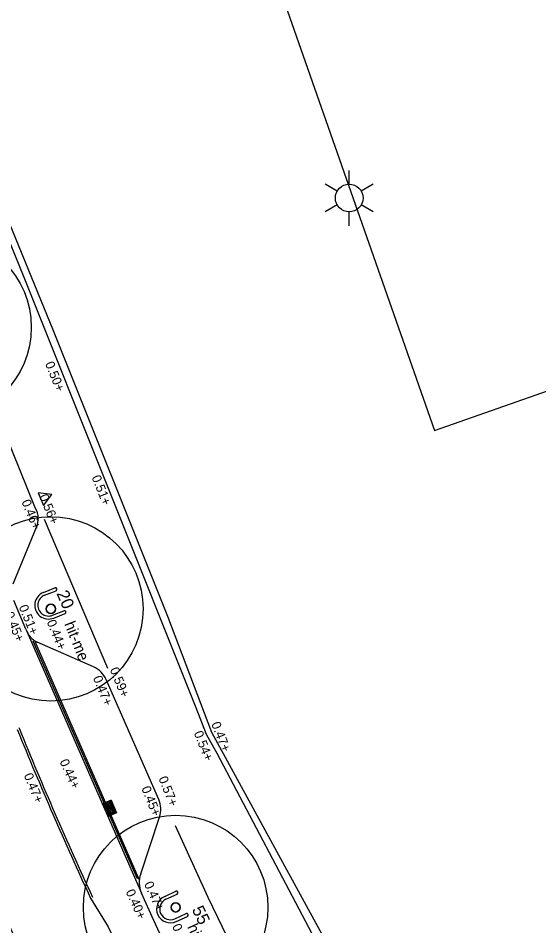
# Model space of a CAD drawing. Extents: x 122462 to 123306, y 485548 to 486417.
# Drawn here: x 122922.68 to 122939.61, y 485863.95 to 485893.49 of the extents above; entities that cross this region are included whole.
import ezdxf

# ---------------------------------------------------------------- set-up
doc = ezdxf.new("R2010")
doc.units = 0
for name, color, linetype in [('B-WE-GR-BOOM_BOOMDIAMETER', 7, 'Continuous'), ('B-WE-IE-TERREINAFSCHEIDING_KUNSTMATIG_HEKWERK-G', 7, 'Continuous'), ('B-WE-OG-HOOGTEPUNT-S', 7, 'Continuous'), ('B-WE-RI-HWA_KOLK-S', 7, 'Continuous'), ('B-WE-VH-KANTOPSLUITING_OPSLUITBAND_100X200-G', 7, 'Continuous'), ('B-WE-VH-KANTOPSLUITING_TROTTOIRBAND_130 150-G', 7, 'Continuous'), ('B-WE-VH-MATERIAALGRENS-G', 7, 'Continuous'), ('B-WE-VH-MATERIAALGRENS_ASFALT-G', 7, 'Continuous'), ('B-WE-VW-MARKERING_LANGS_STREEP_11_010-G', 7, 'Continuous'), ('iba7-verkeersbord rood', 7, 'Continuous'), ('Level 19', 7, 'Continuous'), ('Level 50', 7, 'Continuous'), ('N-WE-GR-BOOM-S', 7, 'Continuous'), ('V markering 1-1 10 cm', 7, 'Continuous'), ('V markering ononderbroken streep 10 cm', 7, 'Continuous'), ('V materiaalscheiding algemeen', 7, 'Continuous'), ('V meubilair trammast', 7, 'Continuous'), ('V Rails', 7, 'Continuous'), ('V RWS-band 115-225x250 mm specie', 7, 'Continuous')]:
    doc.layers.add(name, color=color, linetype=linetype)

msp = doc.modelspace()

# ---------------------------------------------------------------- linework, layer by layer
at = {"layer": 'B-WE-IE-TERREINAFSCHEIDING_KUNSTMATIG_HEKWERK-G'}
msp.add_lwpolyline([(122949.934, 485831.427), (122948.27, 485830.745), (122945.476, 485837.577), (122942.349, 485845.026), (122939.555, 485850.28), (122935.876, 485857.417), (122934.038, 485860.97), (122928.985, 485870.238), (122927.546, 485874.018), (122923.83, 485883.309), (122922.297, 485887.055), (122920.807, 485890.782), (122917.748, 485898.208), (122914.1, 485907.546), (122912.833, 485911.363), (122910.564, 485917.746), (122912.713, 485918.514)], dxfattribs=at)
at = {"layer": 'B-WE-RI-HWA_KOLK-S'}
for p, q in [((122925.702, 485868.036), (122925.427, 485867.917)), ((122925.605, 485867.504), (122925.427, 485867.917)), ((122925.694, 485868.016), (122925.446, 485867.909)), ((122925.694, 485868.016), (122925.861, 485867.631)), ((122925.702, 485868.036), (122925.881, 485867.623)), ((122925.613, 485867.524), (122925.446, 485867.909)), ((122925.881, 485867.623), (122925.605, 485867.504)), ((122925.861, 485867.631), (122925.613, 485867.524))]:
    msp.add_line(p, q, dxfattribs=at)
for points in [[(122925.662, 485867.982), (122925.493, 485867.909)], [(122925.506, 485867.879), (122925.675, 485867.953)], [(122925.682, 485867.936), (122925.513, 485867.863)], [(122925.68, 485867.966), (122925.675, 485867.977)], [(122925.7, 485867.92), (122925.695, 485867.931)], [(122925.488, 485867.896), (122925.493, 485867.885)], [(122925.508, 485867.85), (122925.513, 485867.839)], [(122925.526, 485867.833), (122925.695, 485867.907)], [(122925.528, 485867.804), (122925.532, 485867.793)], [(122925.702, 485867.89), (122925.533, 485867.817)], [(122925.546, 485867.788), (122925.715, 485867.861)], [(122925.548, 485867.758), (122925.552, 485867.747)], [(122925.722, 485867.844), (122925.553, 485867.771)], [(122925.565, 485867.742), (122925.735, 485867.815)], [(122925.567, 485867.712), (122925.572, 485867.701)], [(122925.742, 485867.798), (122925.573, 485867.725)], [(122925.585, 485867.696), (122925.754, 485867.769)], [(122925.587, 485867.666), (122925.592, 485867.655)], [(122925.762, 485867.752), (122925.592, 485867.679)], [(122925.605, 485867.65), (122925.774, 485867.723)], [(122925.607, 485867.62), (122925.612, 485867.609)], [(122925.781, 485867.707), (122925.612, 485867.633)], [(122925.625, 485867.604), (122925.794, 485867.677)], [(122925.801, 485867.661), (122925.632, 485867.588)], [(122925.645, 485867.558), (122925.814, 485867.631)], [(122925.72, 485867.874), (122925.715, 485867.885)], [(122925.74, 485867.828), (122925.735, 485867.839)], [(122925.76, 485867.782), (122925.755, 485867.793)], [(122925.779, 485867.736), (122925.775, 485867.747)], [(122925.799, 485867.69), (122925.795, 485867.701)], [(122925.819, 485867.644), (122925.814, 485867.655)], [(122925.627, 485867.574), (122925.632, 485867.563)]]:
    msp.add_lwpolyline(points, dxfattribs=at)
for centre, start, end in [((122925.666, 485867.973), 23.4005, 113.4005), ((122925.671, 485867.962), 293.4005, 23.4005), ((122925.686, 485867.927), 23.4005, 113.4005), ((122925.691, 485867.916), 293.4005, 23.4005), ((122925.497, 485867.9), 113.4005, 203.4005), ((122925.502, 485867.889), 203.4005, 293.4005), ((122925.517, 485867.854), 113.4005, 203.4005), ((122925.522, 485867.843), 203.4005, 293.4005), ((122925.537, 485867.808), 113.4005, 203.4005), ((122925.542, 485867.797), 203.4005, 293.4005), ((122925.557, 485867.762), 113.4005, 203.4005), ((122925.561, 485867.751), 203.4005, 293.4005), ((122925.577, 485867.716), 113.4005, 203.4005), ((122925.581, 485867.705), 203.4005, 293.4005), ((122925.596, 485867.67), 113.4005, 203.4005), ((122925.601, 485867.659), 203.4005, 293.4005), ((122925.616, 485867.624), 113.4005, 203.4005), ((122925.706, 485867.881), 23.4005, 113.4005), ((122925.711, 485867.87), 293.4005, 23.4005), ((122925.726, 485867.835), 23.4005, 113.4005), ((122925.731, 485867.824), 293.4005, 23.4005), ((122925.746, 485867.789), 23.4005, 113.4005), ((122925.75, 485867.778), 293.4005, 23.4005), ((122925.766, 485867.743), 23.4005, 113.4005), ((122925.77, 485867.732), 293.4005, 23.4005), ((122925.785, 485867.697), 23.4005, 113.4005), ((122925.79, 485867.686), 293.4005, 23.4005), ((122925.805, 485867.652), 23.4005, 113.4005), ((122925.81, 485867.64), 293.4005, 23.4005), ((122925.621, 485867.613), 203.4005, 293.4005), ((122925.636, 485867.578), 113.4005, 203.4005), ((122925.641, 485867.567), 203.4005, 293.4005)]:
    msp.add_arc(centre, 0.01, start, end, dxfattribs=at)
at = {"layer": 'B-WE-VH-KANTOPSLUITING_OPSLUITBAND_100X200-G'}
for points in [[(122946.886, 485834.588), (122946.485, 485834.425), (122944.348, 485839.629), (122942.387, 485844.378), (122942.164, 485844.928), (122941.655, 485845.943), (122937.471, 485853.759), (122929.155, 485869.56), (122928.804, 485870.175), (122928.468, 485871.043), (122922.857, 485885.106), (122919.087, 485894.38), (122914.523, 485905.591), (122913.856, 485907.529), (122911.597, 485914.19)], [(122923.528, 485877.186), (122925.583, 485872.329)], [(122927.784, 485867.211), (122928.85, 485864.878), (122929.63, 485863.27), (122928.026, 485862.478)]]:
    msp.add_lwpolyline(points, dxfattribs=at)
at = {"layer": 'B-WE-VH-KANTOPSLUITING_TROTTOIRBAND_130 150-G'}
for points in [[(122923.249, 485877.529), (122921.74, 485881.238)], [(122922.524, 485875.075), (122923.277, 485876.924)], [(122922.934, 485873.599), (122922.544, 485874.535)], [(122925.133, 485872.372), (122923.299, 485873.184)], [(122927.255, 485868.062), (122925.541, 485871.962)], [(122926.667, 485865.639), (122927.282, 485867.488)], [(122927.946, 485862.264), (122927.091, 485864.122), (122926.688, 485865.016)]]:
    msp.add_lwpolyline(points, dxfattribs=at)
for centre, radius, start, end in [((122922.672, 485877.199), 0.665, 335.5452, 29.7544), ((122923.583, 485873.802), 0.68, 197.3721, 245.2923), ((122924.809, 485871.641), 0.8, 23.7273, 66.115), ((122926.523, 485867.741), 0.8, 341.6022, 23.7273), ((122927.451, 485865.354), 0.834, 159.9979, 203.8632)]:
    msp.add_arc(centre, radius, start, end, dxfattribs=at)
at = {"layer": 'B-WE-VH-MATERIAALGRENS-G'}
msp.add_line((122923.216, 485873.23), (122926.621, 485865.443), dxfattribs=at)
at = {"layer": 'B-WE-VH-MATERIAALGRENS_ASFALT-G'}
msp.add_lwpolyline([(122922.934, 485873.599), (122926.688, 485865.016)], dxfattribs=at)
at = {"layer": 'B-WE-VW-MARKERING_LANGS_STREEP_11_010-G'}
msp.add_line((122923.159, 485873.225), (122926.547, 485865.484), dxfattribs=at)
msp.add_arc((123745.014, 486215.44), 891.767, 202.762333, 202.76555, dxfattribs=at)
at = {"layer": 'iba7-verkeersbord rood'}
for centre, radius in [((122920.109, 485883.423), 3), ((122923.744, 485874.263), 3), ((122923.744, 485874.263), 0.15), ((122927.802, 485864.548), 3), ((122927.802, 485864.548), 0.15)]:
    msp.add_circle(centre, radius, dxfattribs=at)
for centre, start, end in [((122923.744, 485874.263), 0, 180), ((122923.744, 485874.263), 180, 0), ((122927.802, 485864.548), 0, 180), ((122927.802, 485864.548), 180, 0)]:
    msp.add_arc(centre, 0.15, start, end, dxfattribs=at)
at = {"layer": 'Level 19'}
msp.add_lwpolyline([(122932.268, 485910.781), (122926.2, 485908.679), (122936.22, 485880.069), (122952.47, 485885.779)], dxfattribs=at)
at = {"layer": 'Level 50'}
for p, q in [((122933.447, 485888.083), (122933.447, 485888.533)), ((122933.057, 485887.858), (122932.667, 485888.083)), ((122934.226, 485888.083), (122933.836, 485887.858)), ((122933.057, 485887.408), (122932.667, 485887.183)), ((122934.226, 485887.183), (122933.836, 485887.408)), ((122933.447, 485886.733), (122933.447, 485887.183))]:
    msp.add_line(p, q, dxfattribs=at)
msp.add_circle((122933.447, 485887.633), 0.45, dxfattribs=at)
at = {"layer": 'N-WE-GR-BOOM-S'}
for p, q in [((122923.504, 485874.799), (122923.876, 485874.947)), ((122923.541, 485874.706), (122923.913, 485874.854)), ((122923.799, 485874.056), (122924.171, 485874.203)), ((122923.836, 485873.963), (122924.208, 485874.111)), ((122927.447, 485864.906), (122927.811, 485865.072)), ((122927.489, 485864.815), (122927.853, 485864.981)), ((122927.78, 485864.179), (122928.144, 485864.345)), ((122927.821, 485864.088), (122928.185, 485864.254))]:
    msp.add_line(p, q, dxfattribs=at)
for centre, radius, start, end in [((122923.67, 485874.381), 0.45, 111.6607, 291.6607), ((122923.67, 485874.381), 0.35, 111.6607, 291.6607), ((122923.894, 485874.9), 0.05, 291.6607, 111.6607), ((122924.19, 485874.157), 0.05, 291.6607, 111.6607), ((122927.832, 485865.027), 0.05, 294.5412, 114.5412), ((122927.634, 485864.497), 0.45, 114.5412, 294.5412), ((122927.634, 485864.497), 0.35, 114.5412, 294.5412), ((122928.164, 485864.299), 0.05, 294.5412, 114.5412)]:
    msp.add_arc(centre, radius, start, end, dxfattribs=at)
at = {"layer": 'V markering 1-1 10 cm'}
msp.add_arc((123039.536, 485917.817), 126.088, 202.10935, 204.8243, dxfattribs=at)
at = {"layer": 'V markering ononderbroken streep 10 cm'}
msp.add_arc((123193.334, 485981.509), 295.339, 202.64817, 204.42054, dxfattribs=at)
at = {"layer": 'V materiaalscheiding algemeen'}
msp.add_lwpolyline([(122925.034, 485864.852), (122925.605, 485863.912), (122927.792, 485859.303), (122929.313, 485856.858)], dxfattribs=at)
msp.add_arc((123039.759, 485917.917), 126.403, 202.11338, 204.82259, dxfattribs=at)
at = {"layer": 'V meubilair trammast'}
msp.add_lwpolyline([(122923.327, 485878.038), (122923.503, 485877.624), (122923.774, 485877.983)], close=True, dxfattribs=at)
at = {"layer": 'V Rails'}
for radius in [1368.025, 1369.465]:
    msp.add_arc((124176.619, 486407.983), radius, 203.26583, 204.436065, dxfattribs=at)
at = {"layer": 'V RWS-band 115-225x250 mm specie'}
msp.add_arc((123341.297, 486047.345), 457.472, 202.30165, 203.81082, dxfattribs=at)

# ---------------------------------------------------------------- texts
at = {"layer": 'B-WE-GR-BOOM_BOOMDIAMETER'}
for s, rotation, p in [('20', 292.9333, (122923.923, 485874.767)), ('55', 295.8768, (122928.321, 485864.482))]:
    msp.add_text(s, height=0.4, rotation=rotation, dxfattribs=at).set_placement(p)
at = {"layer": 'B-WE-OG-HOOGTEPUNT-S'}
for s, rotation, p in [('0.50+', 292.1389, (122923.55, 485882.243)), ('0.51+', 291.7515, (122925.065, 485878.546)), ('0.56+', 292.1389, (122923.359, 485877.927)), ('0.46+', 292.1389, (122922.785, 485877.751)), ('0.45+', 292.1389, (122922.238, 485874.1)), ('0.51+', 292.1389, (122922.696, 485874.326)), ('0.44+', 292.1389, (122923.604, 485873.841)), ('0.59+', 292.1389, (122925.654, 485872.292)), ('0.47+', 292.1389, (122925.107, 485872.017)), ('0.47+', 291.7515, (122928.954, 485870.521)), ('0.54+', 291.7515, (122928.387, 485870.224)), ('0.44+', 294.4051, (122924.021, 485869.296)), ('0.47+', 292.4976, (122922.856, 485868.847)), ('0.57+', 291.7515, (122927.239, 485868.747)), ('0.45+', 291.7515, (122926.682, 485868.426)), ('0.47+', 294.265, (122926.769, 485865.313)), ('0.40+', 294.265, (122926.172, 485865.058)), ('0.48+', 294.265, (122927.679, 485863.936))]:
    msp.add_text(s, height=0.3, rotation=rotation, dxfattribs=at).set_placement(p)
at = {"layer": 'N-WE-GR-BOOM-S'}
for rotation, p in [(291.6607, (122924.178, 485873.775)), (294.5412, (122928.172, 485863.917))]:
    msp.add_text('hit-me', height=0.36, rotation=rotation, dxfattribs=at).set_placement(p)

doc.saveas('drawing.dxf')
